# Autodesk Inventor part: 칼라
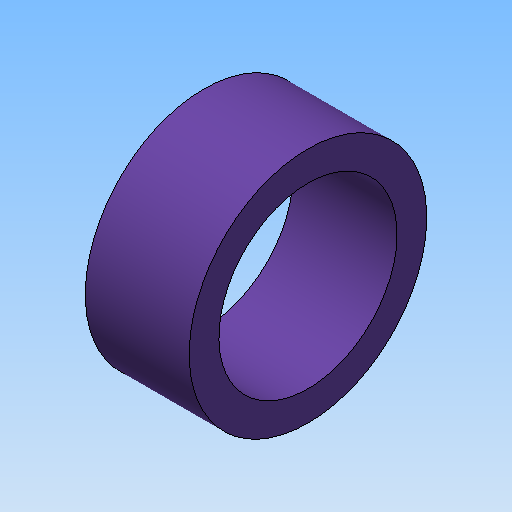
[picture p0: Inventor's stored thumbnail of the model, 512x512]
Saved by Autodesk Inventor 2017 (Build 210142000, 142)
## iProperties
Created: 2020-04
Part Number: 칼라
Material: 강철, 연강
Document SubType Name: Modeling
Designer: mduedu
Density: 7.86 g/cm^3
Mass: 4.83981 g
Surface Area: 7.91681 cm^2
Volume: 0.615752 cm^3
Appearance: 보라색
Author: mduedu
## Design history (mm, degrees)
sketch "스케치1"
  geometry: C1 r 8 at (0, 0); C2 r 6 at (0, 0); 1 further point
  constraints: 2 centre point, 2 coincident
  dimensions: "d0" = 16 diameter of C1; "d1" = 12 diameter of C2
extrude "돌출1" new body sketch "스케치1" distance "d2" = 7; taper "d3" = 0 deg
node "솔리드1"
